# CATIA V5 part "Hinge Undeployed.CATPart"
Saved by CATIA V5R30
Part number: 1
Material "Aluminium": density 2710 kg/m3, Young's modulus 7e+10 Pa, Poisson ratio 0.346, thermal expansion 2.36e-05 1/K
Bounding box of the stored display mesh (mm): x -12.5 to 0, y 0 to 13.591, z 0 to 13.591
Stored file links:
  P:\For real this time GOOD Hinge Undeployed.CATPart
  P:\GOOD Deployed hinge and holder CATPart.CATPart
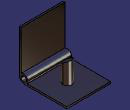
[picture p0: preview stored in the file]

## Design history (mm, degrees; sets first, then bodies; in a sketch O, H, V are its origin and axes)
Body1 (main body), material "Aluminium"
  Sketch1 on xy-plane, origin (0, 0, 0), H (1, 0, 0), V (0, 1, 0)
    point P1 (0, 13.591)
    line L1 (0, 13.591) -> (-12.5, 13.591)
    line L2 (-12.5, 13.591) -> (-12.5, 0)
    line L3 (-12.5, 0) -> (0, 0)
    line L4 (0, 0) -> (0, 13.591)
    point P4 (0, 0)
    length L4 = 13.591
    length L3 = 12.5
    coincidence: P1 V, P4 O
    horizontal: L1 H, L3 H
    vertical: L2 V, L4 V
    fix: L3
  Pad1: profile Sketch1, direction (0, 0, 1), length 0.505
  Sketch2 on zx-plane, origin (0, 0, 0), H (-1, 0, 0), V (0, 0, 1)
    line L1 (0, 0) -> (12.5, 0)
    line L2 (12.5, 0) -> (12.5, 13.591)
    line L3 (12.5, 13.591) -> (0, 13.591)
    line L4 (0, 13.591) -> (0, 0)
    distance L1 L3 = 13.591
    distance L2 L4 = 12.5
    horizontal: L1 H, L3 H
    vertical: L2 V, L4 V
    fix: L1
  Pad2: profile Sketch2, direction (0, 1, 0), length 0.505
  Sketch3 on face of Pad2, origin (0, 0, 0), H (0, 1, 0), V (0, 0, 1)
    circle A1 centre (1.233, 1.233) radius 1.233
    radius A1 = 1.233
    tangency: A1 V, A1 H
  Pad3: profile Sketch3, direction (-1, 0, 0), length 12.5
  Sketch4 on face of Pad3, origin (0, 0, 0), H (0, 1, 0), V (0, 0, 1)
    arc A1 centre (1.233, 1.233) radius 1.233 from (0, 1.233) to (1.233, 0) ccw
    point P1 (0, 1.233)
    point P2 (1.233, 0)
    line L1 (0, 1.233) -> (0, 0)
    line L2 (0, 0) -> (1.233, 0)
    coincidence: P1 V, P2 H
    vertical: L1 V
    horizontal: L2 H
  Pocket1: profile Sketch4, direction (-1, 0, 0), length 12.5
  Sketch5 on face of Pad3, origin (0, 0, 0), H (0, 1, 0), V (0, 0, 1)
    circle A1 centre (1.233, 1.233) radius 0.809
    radius A1 = 0.809
  Pocket2: profile Sketch5, direction (-1, 0, 0), length 12.5
  Sketch6 on end face of Pad1, origin (0, 0, 0.505), H (1, 0, 0), V (0, 1, 0)
    circle A1 centre (-6.25, 7.497) radius 1.369
    point P1 (-6.25, 7.497)
    reference projected line E1 (0, 0) -> (0, 13.591) from edge [face of Pad3 | end face of Pad1]
    reference projected line E2 (-12.5, 13.591) -> (-12.5, 0) from edge [face of Pad3 | end face of Pad1]
    reference projected line E3 (0, 13.591) -> (-12.5, 13.591) from edge [face of Pad1 from Sketch1.L1 | end face of Pad1]
    radius A1 = 1.369
    distance P1 E3 = 6.094
    equidistance: E1 E2 P1
  Pad4: profile Sketch6, direction (0, 0, 1), length 6.4
  Sketch7 on face of Pad3, origin (0, 0, 0), H (0, 1, 0), V (0, 0, 1)
    line L1 (6.128, 5.0025) -> (6.128, 7.7465)
    line L2 (6.128, 5.0025) -> (10.7402, 7.7465)
    line L3 (10.7402, 7.7465) -> (6.128, 7.7465)
    point P3 (6.128, 7.7465)
    angle L2 L3 = 30.75
    length L1 = 2.744
    vertical: L1 V
    horizontal: L3 H
    fix: P3
  Pocket3: profile Sketch7, direction (-1, 0, 0), length 12.5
